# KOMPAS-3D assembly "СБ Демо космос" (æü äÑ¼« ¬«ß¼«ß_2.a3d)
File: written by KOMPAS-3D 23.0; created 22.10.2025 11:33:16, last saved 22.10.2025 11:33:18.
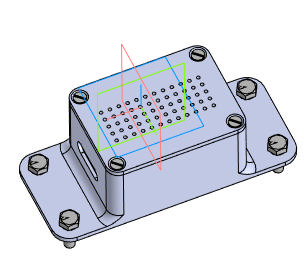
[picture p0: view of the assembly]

Document properties: Автор: ARM_513_VVK; Полное имя файла: F:\Демо\Демо вариант космос\СБ Демо космос_2.a3d

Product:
- Component [assembly]: По умолчанию1  | qty 1  | Масса: 0.636652; Автор: ARM_513_VVK; source file: СБ Демо космос.a3d
- Part/product: СБ Демо космос
    Масса: 0.636652

Referenced files in F:\Демо\Демо вариант космос\: СБ Демо космос.a3d
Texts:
  По умолчанию1 По умолчанию1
